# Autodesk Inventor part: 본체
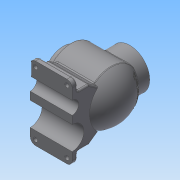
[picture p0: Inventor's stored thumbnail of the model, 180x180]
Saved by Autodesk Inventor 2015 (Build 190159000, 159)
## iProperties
Created: 2018-08
Part Number: 본체
Material: 일반
Document SubType Name: Modeling
Designer: user
Density: 1 g/cm^3
Appearance: 기본값
Author: user
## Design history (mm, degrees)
sketch "스케치1"
  geometry: 1 further point
sketch "스케치2"
  geometry: L1 (0, 0)-(120, 0); L2 (0, 0)-(0, 38); L3 (0, 38)-(12, 38); L4 (12, 38)-(12, 50); L5 (12, 50)-(91.394, 50); A1 r 58 centre (62, 0) between (120, 0) and (91.394, 50)
  constraints: 10 end point, 2 horizontal, 2 perpendicular, 2 point on circle, 1 centre point, 1 horizontal alignment, 1 vertical
  dimensions: "d1" = 38 distance of L1.start L2.end; "d2" = 12 distance of L2.end L3.end; "d7" = 50 distance between parallel lines of L1 L5; "d10" = 116 diameter of A1; "d11" = 108 horizontal distance of L1.end L4.end
revolve "회전1" sketch "스케치2" stored, may be unused: angle "d12" = 90 deg
node "작업 평면1"
sketch "스케치5"
  geometry: L1 (0, 0)-(-82, 0); L2 (-73.171, -50)-(-73.171, -70); L3 (-73.171, -70)-(-83.171, -70); L4 (-83.171, -70)-(-83.171, 70); L5 (-83.171, 70)-(-73.171, 70); L6 (-73.171, 70)-(-73.171, 50); L7 (-73.171, 50)-(-50.839, 50); L8 (-50.839, 50)-(-33.034, 37.533); L9 (-33.034, -37.533)-(-50.839, -50); L10 (-50.839, -50)-(-73.171, -50); A1 r 50 centre (0, 0) between (-33.034, 37.533) and (-33.034, -37.533) reference; A2 r 50 centre (0, 0) between (-33.034, 37.533) and (-33.034, -37.533); 1 further point
  constraints: 20 end point, 4 perpendicular, 4 point on circle, 3 horizontal, 3 horizontal alignment, 1 centre point, 1 coincident, 1 midpoint, 1 vertical alignment, 1 other
  dimensions: "d42" = 82 distance of L1.start L1.end; "d43" = 10 distance of L4.end L5.end; "d44" = 10 distance of L2.end L3.end; "d45" = 140 distance of L3.end L4.end; "d46" = 20 distance of L2.start L2.end; "d47" = 20 distance of L5.end L6.end; "d48" = 35 deg angle of L3 L9
extrude "돌출1" join sketch "스케치5" stored distance "d49" = 80; taper "d50" = 0 deg
sketch "스케치6"
  geometry: L1 (-50, -73.171)-(-70, -73.171) reference; L2 (-70, -73.171)-(-70, -83.171) reference; L3 (-70, -83.171)-(70, -83.171) reference; L4 (70, -83.171)-(70, -73.171) reference; L5 (70, -73.171)-(50, -73.171) reference; L6 (0, 0)-(0, -83.171); C1 r 38 at (0, 0) reference; C2 r 22.5 at (-22.5, -83.171); C3 r 12.5 at (27.5, -83.171); 1 further point
  constraints: 2 centre point, 2 end point, 2 midpoint, 2 point on line, 1 horizontal alignment
  dimensions: "d51" = 45 diameter of C2; "d53" = 22.5 distance of C2.centre L6.end; "d55" = 25 diameter of C3; "d56" = 27.5 distance of C3.centre L6.end
extrude "돌출2" cut sketch "스케치6" stored distance "d57" = 80; taper "d58" = 0 deg
sketch "스케치8"
  geometry: L1 (-12, -50)-(-91.394, -50) reference; L2 (0, 38)-(0, -38) reference; L3 (0, 38)-(0, -38) reference; L4 (-12, 38)-(-12, -38) reference; L5 (-91.394, -37.533)-(-91.394, 37.533) reference; L6 (-91.394, 37.533)-(-91.394, -37.533) reference; L7 (-20, 37.533)-(-91.394, 37.533) reference; L8 (-91.394, -37.533)-(-91.394, 37.533) reference; L9 (-91.394, -37.533)-(-20, -37.533) reference; L10 (-20, -37.533)-(-20, 37.533) reference; L11 (-12, 50)-(-12, -50) reference; C1 r 38 at (-62, 0); 2 further points
  constraints: 1 centre point, 1 horizontal alignment, 1 midpoint
  dimensions: "d59" = 76 diameter of C1; "d60" = 50 distance from line of L4 C1.centre
extrude "돌출3" join sketch "스케치8" distance "d61" = 65; taper "d62" = 0 deg
sketch "스케치9"
  geometry: L1 (0, -38)-(0, 38) reference; L2 (12, -38)-(12, 38) reference; L3 (91.394, 43.818)-(91.394, 43.818) reference; L4 (91.394, 43.818)-(91.394, -33.034) reference; L5 (91.394, -33.034)-(91.394, -33.034) reference; L6 (91.394, -33.034)-(91.394, 43.818) reference; L7 (0, 0)-(110, 0); L8 (0, 0)-(0, 27); L9 (0, 27)-(22, 27); L10 (22, 27)-(22, 40); L11 (22, 40)-(88.533, 40); A1 r 58 centre (62, 0) between (91.394, -50) and (100, 43.818) reference; A2 r 48 centre (62, 0) between (110, 0) and (88.533, 40)
  constraints: 10 end point, 3 perpendicular, 2 point on circle, 1 centre point, 1 horizontal, 1 point on line
  dimensions: "d63" = 27 distance of L7.start L8.end; "d64" = 22 distance of L8.end L9.end; "d65" = 10 radial gap between concentric circles of A1 A2; "d66" = 40 distance between parallel lines of L7 L11
revolve "회전2" sketch "스케치9" stored, may be unused: angle "d67" = 90 deg
sketch "스케치10"
  geometry: C1 r 38 at (0, 0) reference; C2 r 27 at (0, 0); 1 further point
  constraints: 1 centre point, 1 coincident
  dimensions: "d68" = 54 diameter of C2
extrude "돌출4" cut sketch "스케치10" stored distance "d69" = 65; taper "d70" = 0 deg
sketch "스케치11"
  geometry: C1 r 27 at (0, 0) reference; 2 further points
  constraints: 1 horizontal alignment
  dimensions: "d71" = 32.5 distance of point (-32.5, 0) C1.centre
hole "구멍1" sketch "스케치11" at (-32.5, 0) diameter "d72" = 3.242; stored, may be unused: countersink angle "d76" = 90 deg, drill point angle "d78" = 118 deg; dims "d73" = 8, "d74" = 4, "d75" = 2, "d77" = 10
sketch "스케치12"
  geometry: C1 r 27 at (0, 0) reference; 1 further point
  constraints: 1 vertical alignment
  dimensions: "d82" = 32.5 distance of C1.centre point (0, 32.5)
hole "구멍2" sketch "스케치12" at (0, 32.5) diameter "d83" = 3.242; stored, may be unused: countersink angle "d87" = 90 deg, drill point angle "d89" = 118 deg; dims "d84" = 8, "d85" = 4, "d86" = 2, "d88" = 10
sketch "스케치13"
  geometry: L1 (0, 0)-(0, 20) reference; C1 r 4 at (10, 10); C2 r 4 at (70, 10); 2 further points
  constraints: 2 centre point
  dimensions: "d93" = 8 diameter of C1; "d94" = 10 distance from line of L1 C1.centre; "d95" = 10 horizontal distance of L1.end C1.centre; "d96" = 8 diameter of C2; "d97" = 10 horizontal distance of point (80, 20) C2.centre; "d98" = 10 horizontal distance of point (80, 20) C2.centre
extrude "돌출5" cut sketch "스케치13" stored distance "d99" = 65; taper "d100" = 0 deg
node "작업 평면2"
sketch "스케치14"
  geometry: 2 further points
  constraints: 1 horizontal alignment, 1 other
  dimensions: "d103" = 32.5 distance of point (32.5, 0) point (0, 0)
feature "엠보싱1" sketch "스케치14" dims "d1" = 38, "d2" = 12, "d7" = 50, "d10" = 116, "d11" = 108, "d42" = 82, "d43" = 10, "d44" = 10, "d45" = 140, "d46" = 20, "d47" = 20, "d48" = 35 deg, "d104" = 0.5, "d105" = 0
fillet "모깎기1" dims "d106" = 10, "d110" = 3, "d111" = 3, "d112" = 3, "d113" = 3
chamfer "모따기1" distance "d107" = 1; stored, may be unused: second distance "d108" = 2, angle "d109" = 45 deg
node "솔리드1"
pattern_circular "원형 패턴1" dims angle "d80" = 360 deg
pattern_circular "원형 패턴2" dims angle "d91" = 360 deg
mirror "대칭1"
node "투영된 루프2"
node "투영된 루프3"
node "투영된 루프4"
node "투영된 루프5"
node "투영된 루프6"
node "투영된 루프7"
